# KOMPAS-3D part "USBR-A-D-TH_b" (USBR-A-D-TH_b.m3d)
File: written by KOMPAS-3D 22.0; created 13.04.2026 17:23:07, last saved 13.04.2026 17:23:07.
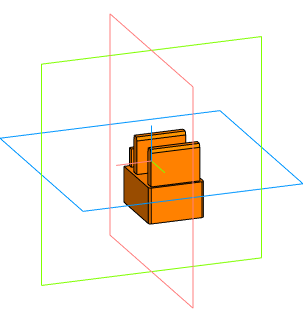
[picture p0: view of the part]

Document properties: Автор: Andrey; Полное имя файла: C:\Users\User1\Documents\USBR-A-D-TH_b.m3d

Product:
- Part/product: USBR-A-D-TH_b
    Комментарий: USBR-A-D-TH_b

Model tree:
1. Операция без истории:1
